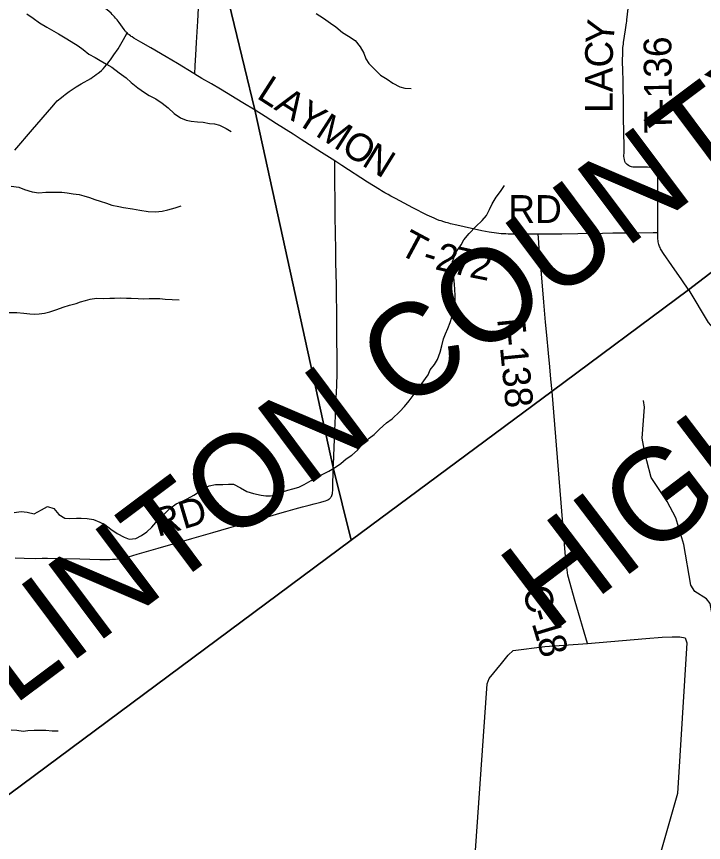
# Model space of a CAD drawing. Extents: x 0 to 1052, y -194 to 246.
# Drawn here: x 5.505 to 6.909, y 17.846 to 19.536 of the extents above; entities that cross this region are included whole.
import ezdxf

# ---------------------------------------------------------------- set-up
doc = ezdxf.new("R2010")
doc.units = 0
for name, color, linetype in [('GM_X_Corporation', 7, 'Continuous'), ('GM_X_County_Road', 7, 'Continuous'), ('GM_X_County_Road_Text', 7, 'Continuous'), ('GM_X_County_Text', 7, 'Continuous'), ('GM_X_Minor_River', 7, 'Continuous'), ('GM_X_Township_Road', 7, 'Continuous'), ('GM_X_Township_Road_Text', 7, 'Continuous')]:
    doc.layers.add(name, color=color, linetype=linetype)

msp = doc.modelspace()

# ---------------------------------------------------------------- linework, layer by layer
at = {"layer": 'GM_X_Corporation'}
for points in [[(5.1788, 17.6981), (5.491, 17.9457), (6.1888, 18.4644), (6.5994, 18.7694), (6.8785, 18.9763), (8.1871, 19.9814), (8.6571, 20.341), (8.7822, 20.435), (8.7822, 21.0055), (1.9822, 21.0055), (1.9822, 14.2055)], [(5.1788, 17.6981), (5.491, 17.9457), (6.1888, 18.4644), (6.152, 18.6129), (5.992, 19.3448), (5.9283, 19.6076), (5.6935, 20.5776), (5.5898, 21.0055), (1.9822, 21.0055), (1.9822, 14.2055)], [(8.7822, 14.2055), (8.7822, 20.435), (8.6571, 20.341), (8.1871, 19.9814), (6.8785, 18.9763), (6.5994, 18.7694), (6.1888, 18.4644), (5.491, 17.9457), (5.1788, 17.6981)], [(8.7822, 14.2055), (8.7822, 19.8853), (8.7716, 19.9458), (8.7665, 19.9791), (8.7595, 20.0343), (8.7564, 20.0663), (8.7504, 20.1046), (8.7444, 20.1332), (8.7375, 20.1583), (8.7292, 20.1831), (8.7137, 20.2216), (8.6781, 20.298), (8.6571, 20.341), (8.1871, 19.9814), (6.8785, 18.9763), (6.5994, 18.7694), (6.1888, 18.4644), (5.491, 17.9457), (5.1788, 17.6981)]]:
    msp.add_lwpolyline(points, dxfattribs=at)
msp.add_lwpolyline([(8.7822, 20.435), (8.7822, 21.0055), (5.5898, 21.0055), (5.6935, 20.5776), (5.9283, 19.6076), (5.992, 19.3448), (6.152, 18.6129), (6.1888, 18.4644), (6.5994, 18.7694), (6.8785, 18.9763), (8.1871, 19.9814), (8.6571, 20.341)], close=True, dxfattribs=at)
at = {"layer": 'GM_X_County_Road'}
for points in [[(6.8787, 18.9758), (6.9182, 18.9098), (6.933, 18.8934), (6.9457, 18.887), (7.2015, 18.8628), (7.5559, 18.8325), (7.6301, 18.8283), (7.7972, 18.8349), (7.8119, 18.8307), (7.8261, 18.8212), (8.0731, 18.6363), (8.1498, 18.5811), (8.209, 18.5397), (8.2345, 18.5273), (8.2518, 18.523), (8.2997, 18.5255), (8.3315, 18.5323)], [(6.6717, 18.2528), (6.6466, 18.3389), (6.6314, 18.3932), (6.6271, 18.4313), (6.5997, 18.7689)], [(6.4234, 17.5474), (6.4665, 18.1706), (6.4706, 18.1815), (6.4957, 18.2123), (6.5098, 18.2294), (6.5195, 18.2387), (6.5846, 18.2468), (6.6717, 18.2528), (6.7911, 18.2633), (6.8246, 18.2663), (6.8451, 18.2668), (6.8602, 18.2668), (6.8716, 18.2646), (6.8747, 18.2547), (6.8555, 17.9462), (6.72, 17.4708)]]:
    msp.add_lwpolyline(points, dxfattribs=at)
at = {"layer": 'GM_X_Minor_River'}
for points in [[(5.5256, 19.541), (5.5384, 19.5325), (5.5516, 19.5229), (5.5663, 19.5141), (5.5761, 19.5083), (5.5901, 19.5006), (5.6041, 19.4925), (5.6165, 19.4844), (5.6309, 19.4755), (5.6407, 19.4682), (5.6527, 19.4586), (5.6652, 19.4521), (5.6757, 19.4455), (5.6886, 19.4382), (5.6995, 19.432), (5.7146, 19.4205), (5.7289, 19.4101), (5.7387, 19.4009), (5.7526, 19.3898), (5.7662, 19.3805), (5.776, 19.374), (5.7893, 19.3671), (5.8025, 19.3586), (5.8145, 19.349), (5.8266, 19.3371), (5.8398, 19.3286), (5.8515, 19.324), (5.8617, 19.3216), (5.8746, 19.3204), (5.886, 19.3195), (5.8992, 19.3171), (5.9095, 19.3162), (5.9197, 19.3135), (5.9329, 19.3069), (5.9431, 19.3004)], [(6.1171, 19.5417), (6.1318, 19.5325), (6.1462, 19.5221), (6.1571, 19.5144), (6.171, 19.5029), (6.1831, 19.4959), (6.1967, 19.4867), (6.2072, 19.4737), (6.2147, 19.4607), (6.2184, 19.4493), (6.2247, 19.4394), (6.2368, 19.4275), (6.2484, 19.416), (6.262, 19.4076), (6.2737, 19.3991), (6.2884, 19.3921), (6.2983, 19.3894), (6.3112, 19.3885)], [(5.4937, 19.1884), (5.509, 19.1867)], [(5.509, 19.1867), (5.5209, 19.1816), (5.5368, 19.1773), (5.5504, 19.1753), (5.5644, 19.1763), (5.5766, 19.1762), (5.5872, 19.1764), (5.5975, 19.1767), (5.6081, 19.1751), (5.6202, 19.1731), (5.6327, 19.1715), (5.6425, 19.1687), (5.6539, 19.1656), (5.6649, 19.1613), (5.6758, 19.1578), (5.6887, 19.1539), (5.6997, 19.15), (5.7137, 19.1468), (5.7235, 19.1448), (5.7417, 19.1424), (5.7569, 19.1396), (5.7735, 19.1372), (5.7887, 19.1363), (5.802, 19.1373), (5.8142, 19.1406), (5.8286, 19.1446), (5.8412, 19.1483)], [(6.4717, 19.1407), (6.4768, 19.1524), (6.4849, 19.1664), (6.4941, 19.1777), (6.5021, 19.1902)], [(5.4999, 18.5214), (5.5142, 18.5231), (5.5263, 18.5215), (5.5407, 18.5183), (5.5556, 18.5265), (5.5681, 18.5336), (5.581, 18.529), (5.5908, 18.5167), (5.6036, 18.5094), (5.6131, 18.5085), (5.6275, 18.5092), (5.637, 18.5098), (5.6491, 18.5086), (5.662, 18.507), (5.6752, 18.5012), (5.6854, 18.4965), (5.6975, 18.4873), (5.7103, 18.4781), (5.7243, 18.4707), (5.7349, 18.4668), (5.7482, 18.4678), (5.7604, 18.4742), (5.7711, 18.4817), (5.781, 18.4911), (5.7937, 18.5054), (5.8059, 18.517), (5.8181, 18.5291), (5.8308, 18.5385), (5.8437, 18.5444), (5.8532, 18.5493), (5.867, 18.5567), (5.8784, 18.5638), (5.8891, 18.5706), (5.8986, 18.5754), (5.9116, 18.5787), (5.9264, 18.5786), (5.9377, 18.5789), (5.9484, 18.5791), (5.9623, 18.5714), (5.9756, 18.5641), (5.9892, 18.5602), (6.0047, 18.5566), (6.0142, 18.5554), (6.024, 18.5553), (6.0343, 18.5571), (6.0484, 18.5631), (6.0594, 18.5667), (6.0693, 18.5693), (6.0815, 18.5726), (6.0925, 18.5786), (6.1067, 18.5868), (6.1181, 18.5932), (6.1307, 18.5995), (6.1433, 18.6055), (6.1566, 18.6137), (6.1677, 18.6212), (6.1784, 18.6306), (6.1902, 18.6384), (6.2017, 18.6486), (6.2121, 18.6606), (6.2254, 18.6734), (6.2358, 18.6809), (6.2469, 18.6914), (6.261, 18.7046), (6.2725, 18.7125), (6.2882, 18.7279), (6.2977, 18.738), (6.3073, 18.7497), (6.3173, 18.7633), (6.3246, 18.7731), (6.3315, 18.7833), (6.3461, 18.8029), (6.3504, 18.8131), (6.3588, 18.824), (6.3654, 18.8342), (6.3708, 18.849), (6.374, 18.8619), (6.3775, 18.8766), (6.3818, 18.8868), (6.3861, 18.8974), (6.3911, 18.9099), (6.3942, 18.9209), (6.3966, 18.9323), (6.3994, 18.9425), (6.401, 18.9538), (6.4015, 18.9652), (6.4008, 18.977), (6.4002, 18.9884), (6.3988, 19.0013), (6.3973, 19.0127), (6.3955, 19.0222), (6.396, 19.0347), (6.3999, 19.0453), (6.4042, 19.0552), (6.4134, 19.0687), (6.4188, 19.0789), (6.4299, 19.0921), (6.4437, 19.106), (6.4563, 19.1185), (6.4655, 19.129), (6.4717, 19.1407)], [(5.5055, 18.9301), (5.5197, 18.9292), (5.5315, 18.9276), (5.5413, 18.9267), (5.5512, 18.9274), (5.5618, 18.9288), (5.5729, 18.9318), (5.587, 18.9362), (5.5999, 18.9414), (5.6132, 18.9454), (5.6262, 18.9487), (5.6357, 18.9521), (5.6456, 18.9546), (5.6551, 18.9572), (5.668, 18.9594), (5.682, 18.9592), (5.6953, 18.9599), (5.7052, 18.9598), (5.7169, 18.9601), (5.7291, 18.9599), (5.7389, 18.9595), (5.7533, 18.9586), (5.7643, 18.9581), (5.7757, 18.9588), (5.7875, 18.959), (5.7977, 18.9586), (5.8087, 18.9573), (5.8368, 18.9563)], [(5.4857, 18.93), (5.5055, 18.9301)], [(7.0535, 18.1981), (6.9981, 18.201), (6.9759, 18.2096), (6.9561, 18.2301), (6.9484, 18.2491), (6.9421, 18.2796), (6.9355, 18.2922), (6.9263, 18.3124), (6.9225, 18.3349), (6.9151, 18.3445), (6.8914, 18.3593), (6.8833, 18.3723), (6.869, 18.4559), (6.8525, 18.5101), (6.8344, 18.5437), (6.8018, 18.5928), (6.7929, 18.6267), (6.79, 18.64), (6.7834, 18.6731), (6.7881, 18.7367), (6.7861, 18.75)], [(5.4937, 18.0762), (5.5052, 18.0757), (5.5181, 18.074), (5.5279, 18.0751), (5.5408, 18.0757), (5.5518, 18.076), (5.5647, 18.0755), (5.5776, 18.0743), (5.5898, 18.0745)]]:
    msp.add_lwpolyline(points, dxfattribs=at)
at = {"layer": 'GM_X_Township_Road'}
for points in [[(5.7306, 19.5021), (5.729, 19.5038), (5.7277, 19.5054), (5.7266, 19.5068), (5.7249, 19.5092), (5.718, 19.5187), (5.7147, 19.5235), (5.7122, 19.5266), (5.71, 19.5292), (5.7071, 19.5326), (5.7048, 19.5353), (5.7024, 19.538), (5.7004, 19.5402), (5.6982, 19.5427), (5.69, 19.5493), (5.6656, 19.5675), (5.6509, 19.5779), (5.6233, 19.5969), (5.6152, 19.6027)], [(6.8155, 19.093), (6.8155, 19.0939), (6.8157, 19.1063), (6.8158, 19.1137), (6.8159, 19.1659), (6.8158, 19.1765), (6.8155, 19.197), (6.8156, 19.2076), (6.8154, 19.2113), (6.8148, 19.215), (6.8139, 19.2173), (6.8129, 19.2195), (6.8114, 19.2215), (6.8101, 19.2229), (6.8076, 19.2246), (6.806, 19.2255), (6.8024, 19.2266), (6.7994, 19.2271), (6.7944, 19.2274), (6.7907, 19.2275), (6.7801, 19.2275), (6.7695, 19.2275), (6.7645, 19.2278), (6.7614, 19.2283), (6.7579, 19.2294), (6.7553, 19.2307), (6.7528, 19.2327), (6.7512, 19.2347), (6.7498, 19.2367), (6.7482, 19.2395), (6.7472, 19.243), (6.7467, 19.246), (6.7463, 19.2503), (6.7464, 19.2585), (6.7464, 19.2697), (6.7455, 19.3287), (6.7451, 19.3641), (6.745, 19.3895), (6.7444, 19.4082), (6.744, 19.4218), (6.7436, 19.4473), (6.7437, 19.4586), (6.7438, 19.4616), (6.7439, 19.4666), (6.7441, 19.4696), (6.7443, 19.4721), (6.7447, 19.4755), (6.7451, 19.4791), (6.7455, 19.4826), (6.7492, 19.5084), (6.7516, 19.5227), (6.752, 19.5255), (6.7524, 19.5287), (6.7595, 19.5935)], [(5.8693, 19.4179), (5.8701, 19.4355), (5.8712, 19.4566), (5.8726, 19.4827), (5.875, 19.5261), (5.8768, 19.5527), (5.877, 19.5551), (5.8773, 19.5577), (5.8778, 19.56), (5.8781, 19.562), (5.8785, 19.5631)], [(5.5009, 19.2625), (5.5373, 19.3049), (5.5767, 19.3505), (5.5845, 19.3594), (5.5879, 19.3631), (5.5905, 19.3654), (5.5935, 19.3681), (5.5963, 19.3704), (5.6004, 19.3735), (5.604, 19.3761), (5.6125, 19.3823), (5.6268, 19.3922), (5.6331, 19.3962), (5.6369, 19.3983), (5.6564, 19.4093), (5.6599, 19.4115), (5.6642, 19.4142), (5.6677, 19.4169), (5.6715, 19.4198), (5.6743, 19.4222), (5.678, 19.4255), (5.6814, 19.429), (5.6848, 19.4326), (5.6877, 19.4361), (5.6903, 19.4392), (5.6934, 19.4432), (5.6964, 19.447), (5.7037, 19.4571), (5.7123, 19.4699), (5.715, 19.4744), (5.718, 19.4794), (5.7207, 19.4843), (5.7233, 19.4889), (5.7265, 19.4946), (5.7306, 19.5021)], [(5.8693, 19.4179), (5.8671, 19.4192), (5.8338, 19.4399), (5.8108, 19.4534), (5.779, 19.4716), (5.7584, 19.4832), (5.7446, 19.4916), (5.7407, 19.494), (5.7391, 19.4951), (5.7374, 19.4964), (5.735, 19.4981), (5.7341, 19.4988), (5.733, 19.4998), (5.7306, 19.5021)], [(5.9922, 19.3443), (5.9675, 19.3595), (5.9217, 19.3871), (5.9029, 19.398), (5.8835, 19.4092), (5.8693, 19.4179)], [(6.1555, 19.2406), (6.1281, 19.2579), (6.0868, 19.2843), (6.0699, 19.2948), (6.0363, 19.3161), (6.0129, 19.3314), (5.9922, 19.3443)], [(6.1522, 18.6124), (6.1525, 18.6191), (6.1554, 18.6886), (6.1566, 18.719), (6.1575, 18.7438), (6.1583, 18.7562), (6.1588, 18.7661), (6.1593, 18.7822), (6.16, 18.8046), (6.16, 18.8116), (6.16, 18.8338), (6.1595, 18.881), (6.1591, 18.9326), (6.1587, 18.9649), (6.1584, 18.9866), (6.1575, 19.0326), (6.1571, 19.0587), (6.1561, 19.1264), (6.1558, 19.1556), (6.1553, 19.2003), (6.1554, 19.2146), (6.1555, 19.2307), (6.1555, 19.2406)], [(6.5709, 19.0905), (6.5419, 19.0906), (6.5096, 19.0908), (6.5046, 19.091), (6.4997, 19.0911), (6.4951, 19.0915), (6.4904, 19.0919), (6.4861, 19.0924), (6.4812, 19.093), (6.4756, 19.0939), (6.4707, 19.0947), (6.4561, 19.0975), (6.4045, 19.1088), (6.3919, 19.1119), (6.3882, 19.1128), (6.3854, 19.1136), (6.3821, 19.1145), (6.3781, 19.1157), (6.3727, 19.1175), (6.3686, 19.1188), (6.364, 19.1206), (6.3614, 19.1218), (6.3583, 19.1231), (6.3442, 19.1297), (6.3149, 19.1446), (6.2791, 19.1633), (6.27, 19.1684), (6.2644, 19.1714), (6.2576, 19.1753), (6.251, 19.1792), (6.2467, 19.1819), (6.2222, 19.1971), (6.1699, 19.2311), (6.1596, 19.238), (6.1555, 19.2406)], [(6.8155, 19.093), (6.8058, 19.093), (6.7625, 19.0928), (6.7233, 19.0923), (6.7022, 19.0921), (6.6519, 19.0913), (6.6196, 19.0906), (6.591, 19.0905), (6.5709, 19.0905)], [(6.5997, 18.7689), (6.597, 18.794), (6.5948, 18.8193), (6.5921, 18.8471), (6.5889, 18.8836), (6.5862, 18.9102), (6.5826, 18.9516), (6.5789, 18.9931), (6.577, 19.0166), (6.573, 19.0618), (6.5715, 19.0828), (6.5709, 19.0905)], [(6.8787, 18.9758), (6.8646, 18.9969), (6.8441, 19.0266), (6.8273, 19.0512), (6.8225, 19.0585), (6.8213, 19.0607), (6.8202, 19.0629), (6.8192, 19.065), (6.8182, 19.0674), (6.8175, 19.0697), (6.8169, 19.0722), (6.8165, 19.0748), (6.816, 19.0777), (6.8158, 19.0806), (6.8156, 19.0839), (6.8155, 19.093)], [(5.5018, 18.4282), (5.5204, 18.4278), (5.5428, 18.4273), (5.557, 18.4274), (5.5676, 18.4274), (5.5918, 18.4269), (5.6341, 18.4261), (5.6751, 18.4251), (5.695, 18.425), (5.7011, 18.4253), (5.7068, 18.4255), (5.7119, 18.426), (5.7172, 18.4268), (5.7212, 18.4276), (5.7258, 18.4285), (5.7301, 18.4296), (5.7336, 18.4305), (5.7515, 18.4356), (5.7938, 18.4481), (5.8631, 18.4681), (5.9061, 18.4804), (5.9384, 18.4894), (6.0005, 18.5073), (6.0226, 18.5138), (6.0429, 18.5195), (6.0554, 18.5232), (6.074, 18.5285), (6.0889, 18.5326), (6.1027, 18.5362), (6.113, 18.5389), (6.1268, 18.5425), (6.1336, 18.5443), (6.1363, 18.5451), (6.1394, 18.5463), (6.1411, 18.5472), (6.1432, 18.5484), (6.1446, 18.5494), (6.1461, 18.5508), (6.1473, 18.5522), (6.1484, 18.554), (6.1493, 18.5559), (6.15, 18.5582), (6.1504, 18.5603), (6.1507, 18.5625), (6.1509, 18.5651), (6.151, 18.5675), (6.1511, 18.5738), (6.1512, 18.5794), (6.1518, 18.603), (6.1522, 18.6124)]]:
    msp.add_lwpolyline(points, dxfattribs=at)

# ---------------------------------------------------------------- texts
at = {"layer": 'GM_X_County_Road_Text'}
for s, rotation, p in [('C', 285.2688, (6.538, 18.3635)), ('-', 286.2693, (6.5506, 18.3175)), ('1', 286.7937, (6.5573, 18.2945)), ('8', 287.0448, (6.5675, 18.2608))]:
    msp.add_text(s, height=0.0568, rotation=rotation, dxfattribs=at).set_placement(p)
at = {"layer": 'GM_X_County_Text'}
for s, rotation, p in [('HIGHLAND COUNTY', 37.2438, (6.5935, 18.2705)), ('CLINTON COUNTY', 36.7754, (5.3509, 18.0148))]:
    msp.add_text(s, height=0.189394, rotation=rotation, dxfattribs=at).set_placement(p)
at = {"layer": 'GM_X_Township_Road_Text'}
for s, height, rotation, p in [('Y', 0.0568, 84.6044, (6.724, 19.4764)), ('C', 0.0568, 88.9188, (6.7232, 19.4309)), ('T-136', 0.05682, 90.5595, (6.845, 19.2967)), ('A', 0.0568, 89.9927, (6.7232, 19.3811)), ('L', 0.0568, 327.375, (5.9933, 19.3701)), ('A', 0.0568, 327.3787, (6.0291, 19.3471)), ('Y', 0.0568, 327.3749, (6.0712, 19.3202)), ('L', 0.0568, 90, (6.7232, 19.3386)), ('M', 0.0568, 327.3789, (6.1133, 19.2932)), ('O', 0.0568, 327.3981, (6.1653, 19.26)), ('N', 0.0568, 328.2727, (6.2082, 19.2325)), ('RD', 0.05682, 0, (6.5097, 19.1135)), ('T', 0.0568, 331.7884, (6.2833, 19.0519)), ('2', 0.0568, 346.8676, (6.3582, 19.0191)), ('7', 0.0568, 347.2827, (6.3927, 19.011)), ('-', 0.0568, 342.5736, (6.3315, 19.0273)), ('2', 0.0568, 348.7347, (6.4284, 19.003)), ('T-138', 0.05682, 275.6002, (6.4857, 18.9305)), ('RD', 0.05682, 16.5575, (5.7933, 18.4709))]:
    msp.add_text(s, height=height, rotation=rotation, dxfattribs=at).set_placement(p)

doc.saveas('drawing.dxf')
